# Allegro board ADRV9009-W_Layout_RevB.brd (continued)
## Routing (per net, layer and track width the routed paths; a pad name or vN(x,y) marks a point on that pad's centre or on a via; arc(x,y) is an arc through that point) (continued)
UNNAMED_9_CN20PV2_I60_N7: length 3.7
  TOP w0.394: TP701.1 52.58,67 P701.13
UNNAMED_9_CN20PV2_I60_N9: length 2.4
  TOP w0.394: R701.2 P701.17
UNNAMED_10_CAP_I51_N1: length 8.5
  TOP w0.127: C314.1 35.5,56.86 35.49,56.85
  TOP w0.394: J303.1 35.49,64.12 35.49,56.85 R309.2
UNNAMED_10_CAP_I60_N1: length 9.6
  TOP w0.203: 34.18,11.3 arc(34.18,11.24) C322.1
  TOP w0.394: J304.1 34.67,6.77 arc(34.61,7.86) 34.42,8.93 arc(34.23,10.05) C322.1 R312.2 34.18,11.3
UNNAMED_10_CAP_I118_N1: length 17.2
  BOTTOM w0.394: R302.1 C301.1 J301.1
UNNAMED_10_CAP_I121_N1: length 3.6
  BOTTOM w0.203: T301.1 21.19,34.55 C303.1
  BOTTOM w0.394: C303.1 20,34.54 ; 20,34.54 21.19,34.55 ; 20,34.54 R302.2
UNNAMED_10_CAP_I142_N1: length 0.8
  TOP w0.133: 33.47,43.47 L323.2
  TOP w0.279: C323.1 33.47,43.47
UNNAMED_10_CAP_I145_N1: length 0.8
  TOP w0.133: 36.21,43.47 L325.2
  TOP w0.279: C325.1 36.21,43.47
UNNAMED_10_CAP_I148_N1: length 0.8
  TOP w0.133: 36.21,24.68 L327.2
  TOP w0.279: C327.1 36.21,24.68
UNNAMED_10_CAP_I152_N1: length 0.8
  TOP w0.133: 33.47,24.68 L329.2
  TOP w0.279: C329.1 33.47,24.68
UNNAMED_10_CAP_I156_N2: length 2
  TOP w0.127: 34.18,14.89 C336.2
  TOP w0.394: 34.18,14.89 C320.1 R312.1
UNNAMED_10_CAP_I157_N2: length 2
  TOP w0.127: 35.5,53.26 C337.2
  TOP w0.394: R309.1 C312.1 35.5,53.26
UNNAMED_10_CAP_I181_N2: length 4.6
  TOP w0.508: C345.2 C344.2 33.59,53.37 C347.2 33.59,53.37 C346.2 33.59,52.16 34.23,51.53 T302.2
UNNAMED_10_CAP_I188_N2: length 4.7
  TOP w0.305: C351.2 36.08,13.05 36.08,13.61 ; C350.2 36.13,13.96 36.08,14.01
  TOP w0.508: 36.08,14.78 C348.2 36.08,15.99 35.45,16.62 T303.2 ; 36.08,14.78 C349.2 ; 36.08,14.78 36.08,13.61
UNNAMED_10_CNBNC3P_I129_CNTR: length 3.9
  BOTTOM w0.394: J305.1 23.24,37.76 24.7,36.3 24.7,35.66 24.07,35.03 R304.1
UNNAMED_10_CNBNC3P_I130_CNTR: length 3.4
  BOTTOM w0.394: J306.1 24.13,31.03 24.13,32.68 R305.1
UNNAMED_11_ADP125_I130_ADJ: length 3.1
  TOP w0.254: U902.3 50.34,2.64 R939.1 R940.2
UNNAMED_11_ADP5054_I29_BST1: length 2
  TOP w0.394: C913.1 84.23,13.91 83.46,13.91 v2(83.45,13.92)
  BOTTOM w0.203: U901.32 v2(83.45,13.92)
UNNAMED_11_ADP5054_I29_BST2: length 2
  TOP w0.394: v2(83.56,11.92) 83.58,11.9 C915.2
  BOTTOM w0.254: U901.28 v2(83.56,11.92)
UNNAMED_11_ADP5054_I29_BST3: length 2
  TOP w0.394: C917.1 93.44,15.92 v2(92.4,15.92)
  BOTTOM w0.254: U901.1 v2(92.4,15.92)
UNNAMED_11_ADP5054_I29_BST4: length 1.7
  BOTTOM w0.254: U901.12 92.86,10.42 C919.1
UNNAMED_11_ADP5054_I29_COMP1: length 2.8
  BOTTOM w0.254: R904.2 87.62,19.06 86.74,18.18 86.74,17.39 86.75,17.38 U901.40
UNNAMED_11_ADP5054_I29_COMP2: length 2.2
  BOTTOM w0.254: R907.2 86.63,7.96 87.25,8.58 U901.20
UNNAMED_11_ADP5054_I29_COMP3: length 2.8
  BOTTOM w0.203: R908.2 90.94,19 90.94,17.86 90.27,17.19 90.27,17.15 90.25,17.13 U901.47
UNNAMED_11_ADP5054_I29_COMP4: length 2.1
  BOTTOM w0.254: U901.15 89.75,8.42 90,8.17 R911.2
UNNAMED_11_ADP5054_I29_DL1: length 5.4
  TOP w0.394: R918.2 81.58,11.52 82.31,11.52 v2(82.33,11.49)
  BOTTOM w0.203: v2(82.33,11.49) 82.99,12.15 82.99,13.06 83.3,13.36 83.94,13.36 83.99,13.42 U901.31
  BOTTOM w0.254: v2(82.33,11.49) 82.31,11.52 Q901.5
UNNAMED_11_ADP5054_I29_DL2: length 9.1
  TOP w0.394: 82.29,14.14 81.17,14.14 v2(78.55,11.52) ; 82.29,14.14 R919.2 ; 82.29,14.14 82.43,14.01 83.55,12.89 v2(83.55,12.76)
  BOTTOM w0.203: v2(83.55,12.76) 83.9,12.42 U901.29
  BOTTOM w0.254: Q901.2 v2(78.55,11.52)
UNNAMED_11_ADP5054_I29_EN1: length 48.1
  L5_SIG w0.394: P902.2 69.13,20.85 72.34,17.64 81.23,17.64 82.68,19.09 84.92,19.09 v2(85.59,18.43) 86.69,17.32 90.18,17.32 91.07,18.21 91.07,18.72 91.58,19.22 93.1,19.22 94.5,17.83 94.5,11.98 92.21,9.7 90.81,9.7 90.36,9.25 v2(90.36,8.7)
  BOTTOM w0.254: U901.39 86.25,17.76 v2(85.59,18.43) R905.2 C911.2 ; U901.14 90.25,8.81 v2(90.36,8.7) 91.03,8.03 R906.1
UNNAMED_11_ADP5054_I29_EN2: length 51.7
  TOP w0.305: R902.2 73.33,19.83 P902.1
  TOP w0.394: v2(86.65,8.8) 86.87,8.59 R903.1
  L5_SIG w0.394: v2(86.65,8.8) 86.65,8.34 85.84,7.53 83.12,7.53 80.78,9.87 80.78,10.33 77.1,14.02 69.61,14.02 66.92,16.71 64.58,16.71 63.64,17.65 63.64,21.38 65.8,23.55 69.62,23.55 P902.1
  BOTTOM w0.254: U901.21 86.75,8.9 v2(86.65,8.8)
UNNAMED_11_ADP5054_I29_EN3: length 35.8
  L5_SIG w0.394: P902.3 71.53,16.56 81.45,16.56 82.43,17.54 84.75,17.54 85.73,16.56 91.07,16.56 91.95,17.44 v2(91.95,18.33)
  BOTTOM w0.203: 90.94,17.06 90.94,16.94 90.75,16.74 U901.48
  BOTTOM w0.254: R912.1 66.6,21.5 P902.3
  BOTTOM w0.394: C912.2 R910.1 R909.2 v2(91.95,18.33) 91.95,18.07 90.94,17.06
UNNAMED_11_ADP5054_I29_FB1: length 38.2
  TOP w0.394: v2(74.41,21.3) 74.41,21.93 76.21,23.74 82.35,23.74 84.08,22.01 84.08,20.27 84.3,20.04 ; 84.3,20.04 85.94,20.04 R914.1 87.72,18.54 87.72,18.38 87.72,18.38 v2(87.72,18.33) ; 84.3,20.04 R916.1
  L5_SIG w0.394: v2(87.72,18.33) 87.72,18.33 87.56,18.33 85.78,20.11 75.59,20.11 v2(74.41,21.3)
  BOTTOM w0.254: v2(87.72,18.33) 87.72,18.18 87.25,17.7 U901.41
  BOTTOM w0.508: 74.41,20.14 R915.1 74.41,20.42 ; 74.41,20.14 74.41,20.42 ; 74.41,20.14 74.41,19.47 74.05,19.11 R917.1 ; 74.41,20.42 v2(74.41,21.3)
UNNAMED_11_ADP5054_I29_FB2: length 21.9
  TOP w0.394: 86.59,6.39 R923.1 ; 86.59,6.39 87.49,6.39 v2(87.59,6.49) ; 86.59,6.39 R920.2
  BOTTOM w0.203: U901.19 87.75,7.89 87.59,7.73 v2(87.59,6.49)
  BOTTOM w0.508: v2(87.59,6.49) 87.52,6.41 87.52,3.73 86.87,3.09 76.06,3.09 R921.1 75.81,3.91 R922.1
UNNAMED_11_ADP5054_I29_FB3: length 13.6
  TOP w0.394: v2(90.28,18.43) 92.02,20.17 94.48,20.17 ; R924.2 94.51,20.21 94.48,20.17 ; R927.1 96.29,20.17 ; 96.29,20.17 94.48,20.17 ; 96.29,20.17 96.29,21.15 v2(96.55,21.4)
  BOTTOM w0.203: U901.46 89.75,17.38 90.28,17.92 v2(90.28,18.43)
  BOTTOM w0.394: R925.1 97.45,21.4
  BOTTOM w0.508: R926.1 96.91,20.08 97.45,20.61 97.45,21.4 v2(96.55,21.4)
UNNAMED_11_ADP5054_I29_FB4: length 20.3
  TOP w0.394: 90.79,7.75 92.29,7.75 R931.1 ; 90.79,7.75 89.18,7.75 v2(89.17,7.73) ; 90.79,7.75 R928.2
  BOTTOM w0.203: U901.16 89.25,7.82 v2(89.17,7.73)
  BOTTOM w0.254: v2(89.17,7.73) 89.17,5.78 89.09,5.7
  BOTTOM w0.508: R930.1 97.55,5.05 R929.1 97.16,4.61 95.63,3.09 89.62,3.09 89.09,3.62 89.09,5.7
UNNAMED_11_ADP5054_I29_PWRGD: length 31.6
  L5_SIG w0.508: v2(66.56,18.72) 67.54,18.72 71.05,15.21 77.18,15.21 81.6,10.78 83.63,10.78 84.59,9.83 86.73,9.83 87.39,9.17 87.39,7.86 v2(88.53,6.72)
  BOTTOM w0.203: v2(88.53,6.72) 88.53,8.09 88.75,8.31 U901.17
  BOTTOM w0.394: v2(66.56,18.72) R912.2
UNNAMED_11_ADP5054_I29_RT: length 2.8
  BOTTOM w0.203: U901.42 87.75,17.49 88.28,18.02 88.28,18.1 88.28,18.1 88.28,18.72 88.63,19.07 R913.1
UNNAMED_11_ADP5054_I29_SW11: length 6.5
  TOP w0.394: C913.2 84.37,15.18 83.53,15.18 v2(83.32,15.38) v2(83.32,14.74)
  BOTTOM w0.254: 79.84,13.2 79.6,12.95 Q901.3 79.81,12.17 80,11.98 Q901.PAD2 ; v2(83.32,14.74) 83.48,14.74 83.8,14.42 U901.33 ; v2(83.32,15.38) 83.36,15.42 U901.35
UNNAMED_11_ADP5054_I29_SW21: length 6.3
  TOP w0.394: v2(82.64,10.07) v2(82.64,9.41) 82.97,9.74 83.58,9.74 C915.1
  BOTTOM w0.254: Q901.PAD1 80.93,11.05 81.11,10.87 Q901.6 ; Q901.6 82.17,10.87 82.38,10.66 ; Q901.6 81.42,10.15 ; U901.25 83.86,10.42 ; U901.27 83.89,11.42 83.58,11.11
UNNAMED_11_ADP5054_I29_SW31: length 4.8
  TOP w0.394: v2(93.13,13.88) v2(93.76,13.88) 93.45,14.2 C917.2
  BOTTOM w0.254: U901.4 92.87,14.42 ; U901.5 93.09,13.92 v2(93.13,13.88)
UNNAMED_11_ADP5054_I29_SW41: length 3.3
  BOTTOM w0.254: C919.2 93.07,11.68 ; 93.07,11.68 93.08,11.68 ; 93.07,11.68 92.83,11.92 U901.9 ; U901.8 92.53,12.42 92.9,12.05
UNNAMED_11_ADP5054_I29_VDD: length 2.9
  TOP w0.394: C903.2 89.22,18.66 v2(88.89,18.33)
  BOTTOM w0.203: v2(88.89,18.33) 88.89,18 88.25,17.36 U901.43
UNNAMED_11_CAP_I25_N2: length 1
  BOTTOM w0.394: R911.1 C910.2
UNNAMED_11_CAP_I27_N2: length 1
  BOTTOM w0.394: C908.2 R908.1
UNNAMED_11_CAP_I30_N2: length 1
  BOTTOM w0.381: C906.2 R907.1
UNNAMED_11_CAP_I32_N2: length 1
  BOTTOM w0.381: R904.1 C904.2
UNNAMED_11_CAP_I54_N1: length 1.4
  BOTTOM w0.508: R929.2 98.54,5.03 C920.1
UNNAMED_11_CAP_I55_N1: length 2.4
  BOTTOM w0.394: R925.2 98.72,21.4
  BOTTOM w0.508: C918.1 99.2,20.13 98.72,20.61 98.72,21.4
UNNAMED_11_CAP_I56_N1: length 1.3
  BOTTOM w0.508: R921.2 74.31,3.85 C916.1
UNNAMED_11_CAP_I59_N1: length 2.2
  BOTTOM w0.508: R915.2 75.68,20.14 75.68,19.44 76.09,19.04 C914.1
UNNAMED_11_CAP_I80_N2: length 2.2
  BOTTOM w0.762: R937.1 C931.2
UNNAMED_11_CAP_I84_N2: length 3.5
  BOTTOM w0.762: C929.2 106.75,17.89 108.45,16.2 R934.1
UNNAMED_11_CAP_I93_N2: length 2.1
  BOTTOM w0.762: R933.1 68.45,9.99 C927.2
UNNAMED_11_CAP_I103_N2: length 2.1
  BOTTOM w0.762: R932.1 68.02,18.35 C924.2
UNNAMED_11_CN2P_I1_N1: length 5.3
  TOP w0.508: 111.2,8.24 P901.1 ; P901.1 111.2,10.91 ; P901.1 112.53,9.57 ; P901.1 109.86,9.57
UNNAMED_11_DIOLED_I8_N: length 2
  TOP w0.203: R901.2 122.49,1.51 122.27,1.72 DS901.C
UNNAMED_11_DIOLED_I179_P: length 2.1
  TOP w0.508: R935.2 DS902.A
VCXO_CON: length 5.5
  BOTTOM w0.394: R407.2 123.62,63.82 123.61,63.8 C406.1 Y402.1 Y401.1
VCXO_CTRL: length 42
  L5_SIG w0.114: v2(126.07,63.82) 123.22,63.82 121.22,61.83 101.16,61.83 94.69,55.35 90.35,55.35 v2(89.88,54.89)
  BOTTOM w0.254: U401.8 90.04,55.43 90.04,55.05 v2(89.88,54.89)
  BOTTOM w0.394: v2(126.07,63.82) R407.1
VCXO_EN: length 5.4
  BOTTOM w0.394: Y401.2 Y402.2 122.22,61.26 122.29,61.2 R409.2 R408.2
VCXO_IN+: length 5.5
  BOTTOM w0.203: C409.2 88.76,50.65 R416.1 88.47,50.97 88.47,55.01 88.54,55.08 88.54,55.37 U401.11
VCXO_IN-: length 5.5
  BOTTOM w0.203: R411.2 87.73,50.67 87.72,50.67 R415.1 88.11,51.02 88.11,55.01 88.04,55.08 88.04,55.3 U401.12
VCXO_OUT+: length 4.5
  BOTTOM w0.203: Y401.4 Y402.4 111.94,58.72 111.22,59.45 R410.1
VCXO_OUT-: length 4.6
  BOTTOM w0.203: R417.1 111.24,60.48 112.03,61.26 Y402.5 Y401.5

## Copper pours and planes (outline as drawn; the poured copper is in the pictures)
AGND on TOP: 0,0 0,21.11 0.62,21.11 0.83,21.5 0.82,23.71 0.62,24.1 0,24.1 0,44.99 0.62,44.99 0.83,45.37 0.82,47.59 0.62,47.97 0,47.98 0,69.09 148.44,69.09 148.44,0 ; 13 cut-outs
AGND on BOTTOM: 0,0 0,9.18 0.58,9.18 0.78,9.56 0.78,11.78 0.58,12.16 0,12.16 0,33.05 0.58,33.05 0.78,33.44 0.78,35.65 0.58,36.03 0,36.04 0,56.93 0.58,56.93 0.78,57.31 0.78,59.53 0.58,59.91 0,59.92 0,69.09 148.44,69.09 148.44,0 ; 15 cut-outs
AGND on L2_GND: 0,0 0,69.09 148.44,69.09 148.44,0 ; 4 cut-outs
AGND on L3_PWR: 0,0 0,69.09 148.44,69.09 148.44,0 ; 3 cut-outs
AGND on L4_GND: 0,0 0,69.09 148.44,69.09 148.44,0 ; 2 cut-outs
AGND on L5_SIG: 0,0 0,69.09 148.44,69.09 148.44,0 ; 34 cut-outs
AGND on L6_GND: 0,0 0,69.09 148.44,69.09 148.44,0 ; 2 cut-outs
AGND on L7_SIG: 0,0 0,69.09 148.44,69.09 148.44,0 ; 28 cut-outs
AGND on L8_SIG: 0,0 0,69.09 148.44,69.09 148.44,0 ; 38 cut-outs
AGND on L9_GND, L11_GND, L13_GND: 0,0 0,69.09 148.44,69.09 148.44,0
AGND on L10_SIG: 0,0 0,69.09 148.44,69.09 148.44,0 ; 3 cut-outs
AGND on L12_PWR: 0,0 0,69.09 148.44,69.09 148.44,0 ; 1 cut-out
VDD1P3_DIG on BOTTOM: 54.1,24.3 51.95,24.3 51.69,24.04 51.69,21.76 52.33,21.12 53.6,21.12 54.49,22.01 54.49,23.92
VDD1P3_DIG on BOTTOM: 71,8.41 71,6.14 70.75,5.89 65.78,5.89 62.99,8.68 61.09,8.68 60.96,8.8 60.96,10.07 61.09,10.2 63.63,10.2 64.39,10.96 66.17,10.96 66.68,10.45 66.68,9.06 66.93,8.8 70.61,8.8
VDD1P3_DIG on L5_SIG: 71,8.81 71,6.02 70.88,5.89 66.16,5.89 63.5,8.55 63.5,9.95 64.52,10.96 66.04,10.96 68.07,8.94 70.88,8.94
VDD1P3_DIG on L8_SIG: 67.73,5.84 70.98,5.84 71.08,5.94 71.08,8.35 68.46,10.97 63.64,10.97 63.13,10.46 63.13,8.3 64.27,7.16 66.4,7.16
VDD_IF_LDO on TOP: 58.05,3.13 58.12,3.21 59.98,3.21 60.21,3.44 60.21,5.63 59.57,6.27 56.78,6.27 56.78,4.75 56.31,4.28 55.89,4.28 55.84,4.23 55.84,3.27 55.98,3.13
VDD_INTERFACE on TOP: 50.75,3.21 49.92,3.22 49.41,2.71 49.41,1.57 48.9,1.06 45.86,1.06 45.35,1.57 45.35,3.35 45.98,3.98 47.38,3.98 49.54,6.14 52.71,6.14 52.84,6.02 52.84,4.78 52.81,4.78 52.81,3.28 52.71,3.18 51.62,3.18 51.49,3.31 50.78,3.31 50.75,3.28
VDD_INTERFACE on L12_PWR: 75.7,22.14 63.76,10.21 54.89,10.21 51.68,7.03 49.41,7.03 45.47,3.09 45.47,1.94 46.74,0.67 69.22,0.67 80.91,12.37 80.91,18.21 89.03,26.33 128.91,26.33 138.19,35.61 138.19,40.31 137.8,40.69 103.51,40.69 98.82,45.39 77.61,45.39 75.7,43.48
VDDA1P3_ANLG on TOP: 59.31,17.06 57.53,15.28 57.53,14.14 58.3,13.37 63.5,13.37 64.14,14.01 71,14.01 71.38,14.39 71.38,16.42 71,16.8 63.5,16.8 63.25,17.06
VDDA1P3_ANLG on BOTTOM: 50.71,19.44 50.55,19.6 49.53,19.6 49.31,19.38 49.31,18.29 49.53,18.07 50.55,18.07 50.71,18.23
VDDA1P3_ANLG on BOTTOM: 67.68,13.36 58.04,13.38 55.76,15.66 55.76,18.07 55.88,18.2 60.45,18.2 61.6,17.06 70.25,17.06 70.45,16.86 70.45,16.13
VDDA1P3_ANLG on L8_SIG: 58.18,16.94 65.78,16.94 66.4,16.31 66.4,14.63 65.8,14.02 63.49,14.02 62.86,13.37 58.17,13.37 57.28,14.26 57.28,16.04
VDDA1P3_ANLG on L12_PWR: 6.48,14.91 12.73,8.66 50.02,8.66 53.85,12.49 63.38,12.49 65.92,15.03 65.92,15.91 62.35,19.48 54.75,19.48 53.98,18.71 45.6,18.71 45.47,18.58 34.17,18.58 30.99,15.41 28.2,15.41 18.93,24.67 18.93,35.35 16.39,37.89 16.39,40.17 18.54,42.33 18.54,54.64 20.8,56.94 21.59,56.94 21.97,57.32 21.97,60.11 19.81,62.27 19.31,62.27 17.91,60.87 17.91,60.11 9.4,51.61 9.41,50.97 6.48,48.05 ; 1 cut-out
VDDA1P3_RF_LO on BOTTOM: 8.26,45 8.77,44.49 9.78,44.49 16.39,37.89 17.27,37.89 17.53,38.14 17.53,39.79 10.04,47.28 9.91,47.28 8.26,45.63
VDDA1P3_RF_SYNTH on BOTTOM: 26.55,58.21 23.75,58.21 22.99,58.97 22.99,61.63 23.12,61.76 24.13,61.76 24.51,62.14 24.51,62.52 24.77,62.78 27.56,62.78 27.69,62.65 27.69,61.13 27.43,60.87 26.8,60.87 26.8,58.46
VDDA1P3_RX_TX on L12_PWR: 26.67,25.82 26.67,28.36 26.55,28.49 26.55,31.15 27.69,32.3 29.72,32.3 30.36,31.66 30.36,30.9 30.1,30.65 29.85,30.65 29.47,31.03 28.83,31.03 28.32,30.52 28.32,26.96 27.05,25.69 26.8,25.69
VDDA1P8_TX on TOP: 103.13,4.99 99.44,4.99 98.94,4.48 98.94,2.83 99.44,2.33 103,2.33 103.25,2.58 103.25,4.87
VDDA1P8_TX on L3_PWR: 81.42,7.29 104.28,7.29 106.03,5.53 106.03,2.37 104.59,0.94 49.94,0.94 43.34,7.54 19.19,7.54 14.54,12.19 14.54,47.85 24.77,58.09 31.24,58.09 31.88,57.44 31.88,55.03 31.63,54.78 29.73,54.78 28.2,53.26 28.2,43.99 26.68,42.46 26.68,37.64 28.08,36.24 28.08,16.18 30.74,13.51 37.46,13.51 37.97,14.02 37.97,19.34 38.86,20.23 43.56,20.23 48.12,15.68 55.8,15.68 61.65,9.83 78.88,9.83
VDDA_1P8 on TOP: 105.03,5.88 103.25,5.88 103.13,5.75 103.13,5.37 103.63,4.87 103.63,2.83 103.76,2.71 104.27,2.71 104.65,3.09 107.7,3.09 108.08,3.47 108.08,5.75 107.7,6.14 105.29,6.14
VDDA_1P8 on BOTTOM: 105.03,5.88 103.25,5.88 103.13,5.75 103.13,5.37 103.51,4.99 103.51,2.45 103.8,2.16 104.86,2.16 105.79,3.09 107.7,3.09 109.48,4.87 109.48,8.04 109.35,8.17 107.7,8.17 107.57,8.04 107.57,6.9 107.32,6.64 105.79,6.64
VDDA_3P3 on TOP: 56.78,7.16 56.78,8.43 57.44,9.09 59.55,9.09 59.83,8.81 59.83,7.29 59.57,7.03 56.91,7.03
VDDA_3P3 on BOTTOM: 107.32,22.27 108.85,20.75 108.85,19.35 108.56,19.06 101.31,19.06 101.23,19.14 101.23,20.36 101.28,20.41 101.71,20.41 101.99,20.68 101.99,23.29 102.75,24.05 104.28,24.05 106.05,22.27
VDDA_3P3 on L3_PWR: 36.07,39.03 35.56,39.54 35.56,39.92 36.2,40.55 39.88,40.55 44.83,45.51 44.83,57.19 45.6,57.95 45.85,57.95 46.48,57.32 46.48,48.05 47.37,47.16 86.62,47.16 105.04,28.75 105.04,20.49 103.39,18.84 99.45,18.84 97.93,20.37 60.21,20.37 56.31,24.27 56.31,37.42 54.7,39.04
VDDA_3P3 on L10_SIG: 71.04,7.63 76.08,2.59 93.86,2.59 102.32,11.05 102.32,12.57 105.55,15.79 105.55,20.87 104.15,22.27 102.63,22.27 101.99,21.64 101.99,21.13 101.23,20.37 97.29,20.37 92.46,15.53 67.06,15.53 65.66,14.14 64.01,14.14 63.25,13.37 61.6,13.37 57.03,8.81 57.03,8.29 58.29,7.03 67.19,7.03 67.81,7.65
1P3_BUCK_OUT on BOTTOM: 80.07,8.67 80.07,5.3 79.92,5.14 71.54,5.14 71.46,5.22 71.46,8.65 71.59,8.78 79.97,8.78
3P3V_CLK1 on BOTTOM: 109.48,17.95 109.48,20.62 109.61,20.75 111.25,20.75 112.09,19.91 112.09,18.14 111.64,17.7 109.74,17.7
3P3V_CLK1 on L3_PWR: 146.34,19.16 128.41,19.16 125.87,21.7 121.87,21.7 119.96,19.8 114.12,19.8 112.28,17.95 109.74,17.95 109.1,18.59 109.1,26.84 111.64,29.38 137.52,29.38 140.79,32.66 140.79,49.42 138.99,51.22 88.39,51.22 82.81,56.81 82.81,65.19 84.72,67.11 107.7,67.09 107.95,66.84 107.95,62.9 111.02,59.84 144.91,59.87 147.38,57.4 147.38,20.21
3P3V_CLK1 on L10_SIG: 81.92,54.49 82.44,53.97 97.3,53.97 97.75,54.43 97.75,67.53 97.16,68.12 82.43,68.12 81.92,67.61
3P3V_VCXO on L3_PWR: 110.75,65.32 110.75,63.67 112.6,61.81 126.91,61.81 127.24,62.14 127.24,66.81 126.99,67.07 112.5,67.07
3P3VAUX on L12_PWR: 112.4,21.13 112.4,16.56 112.87,16.09 126.53,16.09 126.83,16.4 139.59,16.4 139.76,16.57 139.76,21.35 139.46,21.65 112.93,21.65
FMCA_VADJ on L12_PWR: 127.04,9.13 127.04,6.54 127.14,6.44 132.83,6.44 133.03,6.64 133.03,8.57 133.82,9.36 139.2,9.36 139.43,9.59 139.43,11.87 139.31,12 130.75,12 130.7,11.95 130.7,9.51 130.44,9.26 127.17,9.26
FMCA_VCC_3P3V on L12_PWR: 126.96,9.94 127.05,9.86 130.05,9.86 130.16,9.97 130.16,12.33 130.57,12.74 139.26,12.74 139.84,12.15 139.84,9.21 139.94,9.11 142.68,9.11 142.79,9.21 142.79,15.48 142.58,15.68 127.04,15.68 126.96,15.61
FMCA_VCC_12P0V on TOP: 120.67,9.69 130.18,9.69 132.07,11.58 132.07,12.22 132.49,12.64 142.48,12.64 142.61,12.76 142.61,16.55 142.43,16.73 140.86,16.73 140.75,16.62 140.75,15.95 140.34,15.54 130.31,15.54 129.17,14.4 124.98,14.4 123.83,15.54 117.74,15.54 117.48,15.29 117.48,12.87
INPUT_VOLTAGE on TOP: 125.61,6.65 117.55,6.65 117.17,6.27 117.17,4.11 117.55,3.73 125.61,3.73 125.93,4.05 125.93,6.33
INPUT_VOLTAGE on BOTTOM: 85.71,16.27 84.95,16.27 84.87,16.19 84.87,15.84 84.82,15.79 83.5,15.79 83.45,15.84 83.05,15.84 82.87,16.01 82.87,20.08 82.89,20.1 84.65,20.1 84.7,20.05 84.7,18.3 85.76,17.23 85.76,16.32
INPUT_VOLTAGE on BOTTOM: 100.77,14.67 100.77,10.43 100.67,10.33 98.54,10.33 98.42,10.44 98.42,14.73 98.49,14.8 100.65,14.8
INPUT_VOLTAGE on BOTTOM: 85.86,6.62 85.76,6.52 83.93,6.52 83.83,6.62 83.83,8.8 84.98,9.94 86.02,9.94 86.07,9.89 86.07,8.93 85.86,8.72
INPUT_VOLTAGE on L12_PWR: 102.24,14.65 117.61,14.65 125.93,6.33 125.93,4.05 125.1,3.22 106.68,3.22 103.89,6.02 84.69,6.02 82.89,7.81 82.89,18.29 85.29,20.68 96.21,20.68
TX1_BAL+ on TOP (solid shape): 34.57,46.94 34.77,46.5 34.85,46.02 34.85,45.04 34.83,44.98 34.78,44.96 34.11,44.96 34.06,44.98 34.04,45.04 34.04,46.02 34,46.45 33.85,46.85 33.86,47.69 34.57,47.69
TX1_OUT+ on TOP (solid shape): 34.71,44.68 34.76,44.66 34.78,44.6 34.78,40 34.76,39.81 34.67,39.64 34.6,39.53 34.56,39.4 34.56,39.25 34.5,39.19 34.38,39.19 34.31,39.26 34.31,39.39 34.25,39.56 34.11,39.66 34.02,39.72 33.97,39.81 33.97,44.6 33.99,44.66 34.05,44.68
TX1_OUT- on TOP (solid shape): 35.63,44.68 35.68,44.66 35.7,44.6 35.7,39.81 35.65,39.72 35.56,39.66 35.42,39.56 35.36,39.39 35.36,39.25 35.3,39.19 35.17,39.19 35.11,39.25 35.11,39.4 35.08,39.53 35,39.64 34.92,39.81 34.89,40 34.89,44.6 34.91,44.66 34.97,44.68
TX2_BAL+ on TOP (solid shape): 35.56,23.19 35.62,23.17 35.64,23.11 35.64,22.13 35.68,21.7 35.83,21.31 35.81,20.46 35.11,20.46 35.11,21.21 34.9,21.65 34.82,22.13 34.82,23.11 34.84,23.17 34.9,23.19
TX2_OUT+ on TOP (solid shape): 35.36,28.9 35.36,28.76 35.43,28.6 35.57,28.49 35.65,28.44 35.71,28.34 35.71,23.55 35.69,23.49 35.63,23.47 34.97,23.47 34.92,23.49 34.89,23.55 34.89,28.15 34.92,28.34 35,28.51 35.08,28.62 35.11,28.76 35.11,28.9 35.17,28.96 35.3,28.96
TX2_OUT- on TOP (solid shape): 34.57,28.9 34.57,28.76 34.6,28.62 34.68,28.51 34.76,28.34 34.78,28.15 34.78,23.55 34.76,23.49 34.71,23.47 34.05,23.47 33.99,23.5 33.97,23.55 33.97,28.34 34.02,28.44 34.11,28.49 34.25,28.6 34.31,28.76 34.31,28.9 34.37,28.96 34.5,28.96
UNNAMED_4_CAP_I274_N1 on BOTTOM: 107.59,60.77 107.59,59.22 107.49,59.12 105.89,59.12 105.84,59.17 105.84,60.77 105.89,60.82 107.54,60.82
UNNAMED_5_CNTP1P_I268_N1 on BOTTOM: 24.01,62.02 21.47,62.02 21.34,62.14 21.34,64.68 21.59,64.94 24.13,64.94 24.39,64.68 24.39,63.41 24.13,63.16 24.13,62.14
UNNAMED_11_ADP5054_I29_SW11 on BOTTOM: 84.9,15.43 84.9,14.54 84.85,14.49 83.32,14.49 81.83,12.99 81.29,12.99 80.78,12.48 80.78,11.98 80.66,11.85 79.95,11.85 79.82,11.98 79.44,11.98 79.39,12.03 79.39,12.94 80.38,13.93 80.38,17.69 80.45,17.77 82.16,17.77 82.26,17.67 82.26,15.74 82.41,15.58 83.86,15.58 83.99,15.46 84.87,15.46
UNNAMED_11_ADP5054_I29_SW21 on BOTTOM: 84.06,10.25 82.99,9.18 82.99,5.09 82.94,5.04 80.66,5.04 80.58,5.12 80.58,10.48 80.28,10.78 80.28,11.34 80.3,11.37 81.01,11.37 81.37,11.01 82.77,11.01 83.05,11.29 84.85,11.29 84.9,11.24 84.9,10.58 84.57,10.25
UNNAMED_11_ADP5054_I29_SW31 on BOTTOM: 97.85,13.07 92.7,13.07 92.57,13.2 92.57,14.59 92.62,14.64 97.85,14.64 97.9,14.59 97.9,13.12
UNNAMED_11_ADP5054_I29_SW41 on BOTTOM: 93.71,10.78 92.54,10.78 92.49,10.83 92.49,12.33 92.72,12.56 97.83,12.56 97.88,12.51 97.88,10.58 97.8,10.5 93.99,10.5
UNNAMED_11_CAP_I54_N2 on BOTTOM: 94.09,8.19 94.09,9.69 94.17,9.77 101.41,9.77 101.64,9.99 104.97,9.99 105.15,9.81 105.16,8.67 105.54,8.29 106.81,8.29 107.06,8.04 107.06,7.28 106.94,7.15 105.16,7.15 104.37,6.36 96.35,6.36 96.3,6.41 96.3,8.06 96.23,8.14 94.15,8.14
UNNAMED_11_CAP_I55_N2 on BOTTOM: 94.09,16.88 94.09,15.38 94.17,15.3 101.41,15.3 101.64,15.07 107.07,15.07 107.07,16.35 104.91,18.5 100.75,18.5 100.55,18.71 96.35,18.71 96.3,18.66 96.3,17.01 96.23,16.93 94.15,16.93
UNNAMED_11_CAP_I59_N2 on BOTTOM: 79.82,17.56 79.82,14.19 79.67,14.03 70.73,14.03 70.65,14.11 70.65,15.3 71.01,15.66 71.01,17.01 71.11,17.11 72.76,17.11 73.32,17.67 79.72,17.67
UNNAMED_11_CN2P_I1_N1 on TOP: 111.83,15.35 111.83,11.86 113.04,10.65 113.04,8.49 112.34,7.79 109.99,7.79 109.36,8.43 109.36,15.29 109.61,15.54 111.64,15.54
UNNAMED_11_DIO_I7_P on TOP: 113.42,15.54 113.23,15.35 113.23,11.29 114.06,10.46 114.06,8.56 114.82,7.79 122.31,7.8 122.82,8.3 122.82,10.33 122.31,10.84 118.75,10.84 116.47,13.13 116.47,15.29 116.21,15.54

Small or netless copper shapes (teardrops, artwork), in the pictures only: 6 on TOP, 5 on BOTTOM

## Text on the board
Ref Des/Silkscreen Bottom: RX_EXT_LO_I/O | RX1 | ORX1 | RX2 | ORX2 | TX2 | TX1
Ref Des/Silkscreen Top: RX_EXTLO_I/0 | VDDA1P3_ | AUX_VCO_LDO | RF_VCO_LDO | VDDA1P3_RX_TX | VDDA1P3_RX_RF | GND | ANLG | POWER_OK | VOUT3_3V3 | REF_CLK_IN | 6.0-12.0V DC | 2A MAX | STATUS1 | STATUS2 | SYNCOUTB1- | FMCA_VCC_12P0V | SYNCINB0- | SYNCOUTB1+ | SYNCOUTB0- | SYNCOUTB0+ | SYNCINB0+ | FMCA_VCC_3P3V | VDDA1P8_BB | VDDA1P3_BB | CLOCK_SYNTH | GPIO_3P3 | VCO_LDO | VDDA1P3_CLK_ | 10 | 11 | VDDA1P3_SER | 8 | 9 | VDDA1P3_DES | 6 | 7 | 4 | 5 | TX1_EN | TX2_EN | RX1_EN | RX2_EN | 2 | 3 | VTUNE | RF_SYNTH_ | AUX_SYNTH_ | 0 | 1 | GPIO_1 | GPIO_18 | GPIO_15 | GPIO_14 | AUXADC3 | GPIO_12 | AUXADC2 | AUXADC1 | GPIO_10 | AUXADC0 | GPIO_8 | GPIO_9 | GPIO_7 | GPIO_6 | GPIO_0 | VDDA1P8_TX | SPI_DOUT_9528 | V_IN | SPI_DOUT | SYNCINB1+ | SPI_DOUT_DUT | SYNCINB1- | SPI_CLK | TEST | SPI_CSI | SPI_DIN | GP_INTERRUPT | FMCA_VADJ | RESETB | VDDA1P3_RF_LO | AUX_SYNTH | RF_SYNTH | ORX1 | RX1 | RX2 | ORX2 | POWER_IN | TX2 | TX1 | ADRV9009-W/PCBZ
DIMENSION: .087" | 30 DEGREES BOTH SIDES | SCORE DETAIL | SCORE EDGE | WEB .020 +/- .004
PAGE_OUTLINE: B | AS PER ECR-074509 | 19JAN18 | N.PARIKH
User.15: CHARACTERISTIC IMPEDANCE = 100 OHMS +/- 10% DIFF PAIR | ARTWORK LINE WIDTH FOR | IMPEDANCE CONTROLLED LINES = 0.008"/0.006 AND 0.0036"/0.0064" | CHARACTERISTIC IMPEDANCE = 50 OHMS +/- 10% DIFF PAIR | IMPEDANCE CONTROLLED LINES = 0.032"/0.004" | ISOLA 370HR | ROGERS4003 | 50 OHMS 0.0045" SINGLE ENDED / 100 OHMS 0.0036"/0.0064" DIFF | 50 OHMS 0.0155" SINGLE ENDED; 0.032"/0.004" DIFF | 50 OHMS 0.0155" SINGLE ENDED / 100 OHMS 0.008"/0.006" DIFF | 100 OHMS 0.008"/0.006" DIFF | SEE NOTE 15
User.17: 08-      -07 | L2 GND
User.18: L3 PWR | 08-      -08
User.19: L4 GND | 08-      -09
User.20: 08-      -10 | L5 SIG
User.22: 08-      -11 | L6 GND
User.23: 08-      -12 | L7 SIG
User.24: 08-      -13 | L8 SIG
User.25: 08-      -14 | L9 GND
User.26: 08-      -15 | L10 SIG
User.27: L11 GND | 08-      -16
User.28: L12 PWR | 08-      -17
User.29: 08-      -18 | L13 GND
User.45: NOTES: | - MNC_LAYER: MUST-NOT-CUT-LAYER | - MAX_DEPTH: DEPTH FROM START LAYER TO THE | SURFACE OF MUST-NOT-CUT-LAYER | - MFG_STUB : MANUFACTURING STUB LENGTH | FIGURE | SIZE | 6.0 | 8.0 | 10.0 | 20.0 | 40.0 | 45.0 | 60.0 | 65.0 | 70.0 | 50.0 | 100.0 | 160.0 | 6.01 | 10.01 | 10.02 | PLATED | NON-PLATED | DRILL CHART: TOP to BOTTOM | ALL UNITS ARE IN MILS | DRILL CHART: TOP to L10_SIG | DRILL CHART: L11_GND to BOTTOM | QTY | 101 | 288 | 1052 | 103 | 43 | 69 | 5 | 2 | 8 | 109 | 106 | 14 | 136 | +3.0/-3.0 | +0.0/-0.0 | +2.0/-2.0 | TOLERANCE/NOTES | BD_SIZE | 18.0 | MNC_Layer | L5_SIG | L10_SIG | BACKDRILL: TOP to L4_GND | BACKDRILL: TOP to L9_GND | MAX_DEPTH | 26.22 | 50.38 | MFG_STUB | 3.0 | 6
